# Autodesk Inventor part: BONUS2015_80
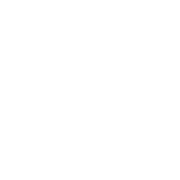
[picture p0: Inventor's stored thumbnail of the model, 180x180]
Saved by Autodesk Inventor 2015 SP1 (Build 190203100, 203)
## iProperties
Created: 2015-05
Part Number: BONUS2015_80
Material: Generisch
Document SubType Name: Modeling
Density: 1 g/cm^3
Appearance: Vorgabe
xx: 80
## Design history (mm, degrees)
